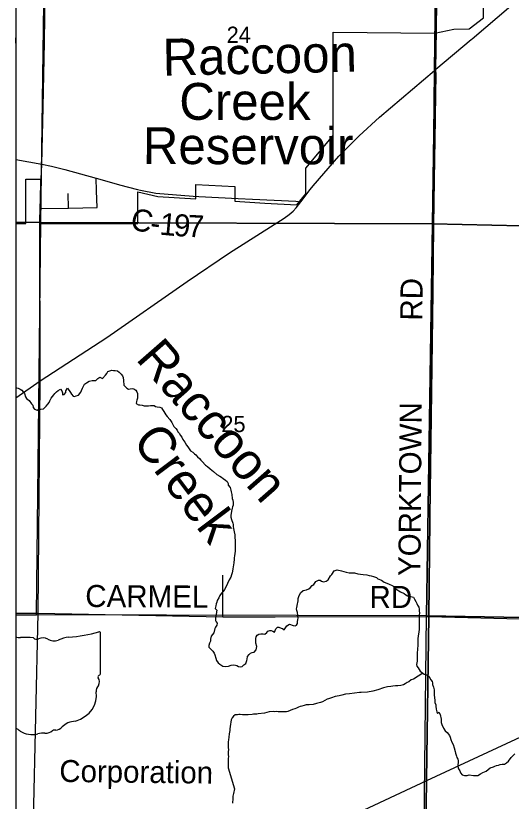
# Model space of a CAD drawing. Extents: x 0 to 34, y 0 to 22.
# Drawn here: x 2.1 to 3.375, y 14.74 to 16.762 of the extents above; entities that cross this region are included whole.
import ezdxf

# ---------------------------------------------------------------- set-up
doc = ezdxf.new("R2010")
doc.units = 0
for name, color, linetype in [('Default', 7, 'Continuous'), ('GM_X_City_Street', 7, 'Continuous'), ('GM_X_County_Road', 7, 'Continuous'), ('GM_X_County_Road_Text', 7, 'Continuous'), ('GM_X_Minor_Lake', 7, 'Continuous'), ('GM_X_Minor_Lake_Text', 7, 'Continuous'), ('GM_X_Minor_River', 7, 'Continuous'), ('GM_X_Minor_River_Text', 7, 'Continuous'), ('GM_X_Rail_Line_Text', 7, 'Continuous'), ('GM_X_Section', 7, 'Continuous'), ('GM_X_Section_Text', 7, 'Continuous'), ('GM_X_State_Location', 7, 'Continuous'), ('GM_X_State_Route', 7, 'Continuous'), ('GM_X_Township_Road', 7, 'Continuous'), ('GM_X_Township_Road_Text', 7, 'Continuous'), ('GM_X_Unincorporated_Text', 7, 'Continuous'), ('SH_Cut_Line', 7, 'Continuous'), ('SH_Data', 7, 'Continuous')]:
    doc.layers.add(name, color=color, linetype=linetype)

msp = doc.modelspace()

# ---------------------------------------------------------------- linework, layer by layer
at = {"layer": 'Default'}
msp.add_lwpolyline([(2.1, 18.4765), (2.1, 16.2268), (2.1261, 16.2272), (2.1261, 16.3412), (2.164, 16.3412), (2.1619, 16.2272), (2.4141, 16.2273), (2.4146, 16.3086), (2.4658, 16.2966), (2.5633, 16.2906), (2.5633, 16.3276), (2.664, 16.3223), (2.664, 16.2844), (2.741, 16.2797), (2.8235, 16.2748), (2.8465, 16.3036), (2.8465, 16.3697), (2.9169, 16.4536), (2.9169, 16.7199), (3.1786, 16.7169), (3.2272, 16.7274), (3.2668, 16.728), (3.3042, 16.7562), (3.3042, 16.7883)], dxfattribs=at)
for points in [[(2.1, 17.2332), (2.1, 16.2301), (2.1648, 16.2299), (2.1787, 17.2327)], [(2.1, 16.2301), (2.1, 15.22), (2.1535, 15.22), (2.1648, 16.2299)]]:
    msp.add_lwpolyline(points, close=True, dxfattribs=at)
at = {"layer": 'GM_X_City_Street'}
msp.add_line((2.236, 16.2668), (2.2354, 16.3044), dxfattribs=at)
for points in [[(2.3093, 16.2682), (2.3082, 16.3112), (2.3073, 16.3437)], [(2.1626, 16.2653), (2.236, 16.2668), (2.3093, 16.2682)]]:
    msp.add_lwpolyline(points, dxfattribs=at)
at = {"layer": 'GM_X_County_Road'}
for p, q in [((3.1811, 16.6243), (3.2725, 16.7007)), ((2.1, 16.3918), (2.1675, 16.3795)), ((2.8339, 16.2826), (2.8579, 16.3145)), ((2.5714, 16.2968), (2.6722, 16.2916)), ((2.1, 15.7781), (2.1627, 15.8218)), ((2.1481, 14.3195), (3.1578, 14.7935))]:
    msp.add_line(p, q, dxfattribs=at)
for points in [[(3.2725, 16.7007), (3.2748, 16.7027), (3.3741, 16.7874), (3.4093, 16.8175), (3.4389, 16.8423)], [(2.8579, 16.3145), (2.8651, 16.3241), (2.9317, 16.4007), (2.9842, 16.4531), (3.036, 16.5009), (3.1776, 16.6213), (3.1811, 16.6243)], [(2.1675, 16.3795), (2.192, 16.3743), (2.2263, 16.3658), (2.3073, 16.3437), (2.3528, 16.331)], [(2.3528, 16.331), (2.3673, 16.327), (2.4134, 16.3146), (2.4214, 16.313)], [(2.4214, 16.313), (2.4605, 16.3054), (2.5563, 16.2976), (2.5714, 16.2968)], [(2.1627, 15.8218), (2.3342, 15.9332), (2.541, 16.0775), (2.6502, 16.1519), (2.7651, 16.2248), (2.7906, 16.2409), (2.8037, 16.2498), (2.8142, 16.2591), (2.8217, 16.2673), (2.8339, 16.2826)], [(2.6722, 16.2916), (2.7095, 16.2897), (2.8212, 16.2843), (2.8339, 16.2826)], [(3.1578, 14.7935), (3.6526, 15.0232), (3.9337, 15.154), (4.0209, 15.1945), (4.1568, 15.2599), (4.2108, 15.2852), (4.2951, 15.3262), (4.5042, 15.4319), (4.6673, 15.5158)]]:
    msp.add_lwpolyline(points, dxfattribs=at)
at = {"layer": 'GM_X_Minor_Lake'}
for p, q in [((2.1, 16.691), (2.1002, 16.7053)), ((2.1002, 16.7053), (2.1, 16.7053))]:
    msp.add_line(p, q, dxfattribs=at)
at = {"layer": 'GM_X_Minor_River'}
msp.add_line((2.1002, 16.7053), (2.1002, 16.7053), dxfattribs=at)
for points in [[(2.2206, 15.7863), (2.2248, 15.7867), (2.2286, 15.7924), (2.2289, 15.7962), (2.2335, 15.803), (2.2407, 15.7921), (2.2434, 15.7875), (2.2476, 15.7826), (2.2514, 15.7819), (2.2556, 15.7834), (2.262, 15.7853), (2.2673, 15.7926), (2.2696, 15.7975), (2.2718, 15.8028), (2.2744, 15.8082), (2.2771, 15.8131), (2.282, 15.8169), (2.2888, 15.8212), (2.2968, 15.8227), (2.3028, 15.8231), (2.3066, 15.8228), (2.3112, 15.8281), (2.3168, 15.8312), (2.3233, 15.8278), (2.3308, 15.8366), (2.3346, 15.8411), (2.3369, 15.8457), (2.3426, 15.848), (2.3471, 15.8495), (2.3517, 15.8488), (2.3558, 15.8488), (2.3619, 15.8477), (2.3661, 15.8439), (2.3711, 15.8394), (2.3749, 15.8349), (2.3768, 15.8307), (2.3772, 15.8231), (2.3784, 15.8106), (2.3822, 15.8068), (2.3857, 15.803), (2.3906, 15.8004), (2.3944, 15.8015), (2.4001, 15.8019), (2.4039, 15.8016), (2.4089, 15.7982), (2.4119, 15.7933), (2.4135, 15.7891), (2.4135, 15.7815), (2.4131, 15.7773), (2.4113, 15.7724), (2.4109, 15.7686), (2.4102, 15.764), (2.4159, 15.7602), (2.4197, 15.7599), (2.4254, 15.7591), (2.4307, 15.758), (2.4356, 15.7573), (2.4417, 15.7577), (2.447, 15.7581), (2.4508, 15.7585), (2.4561, 15.7585), (2.4599, 15.7563), (2.4637, 15.7555), (2.4706, 15.754), (2.4751, 15.7522), (2.4778, 15.7484), (2.4813, 15.7427), (2.4839, 15.7385), (2.4862, 15.7343), (2.4901, 15.7298), (2.4962, 15.7222), (2.5015, 15.7151), (2.5034, 15.7113), (2.5073, 15.7048), (2.5122, 15.6991), (2.5153, 15.6946), (2.5176, 15.6908), (2.521, 15.687), (2.5241, 15.6813), (2.5275, 15.6772), (2.5302, 15.6711), (2.5356, 15.6639), (2.5398, 15.6567), (2.5428, 15.6522), (2.5463, 15.6473), (2.5501, 15.6416), (2.5554, 15.6382), (2.56, 15.6344), (2.5638, 15.6314), (2.5676, 15.6261), (2.573, 15.6219), (2.5764, 15.6182), (2.5795, 15.614), (2.5882, 15.6053), (2.5936, 15.6011), (2.6008, 15.5955), (2.6092, 15.5887), (2.618, 15.5811), (2.6252, 15.5766), (2.6294, 15.5736), (2.634, 15.5706)], [(2.1, 15.8053), (2.1021, 15.8036), (2.1059, 15.8028), (2.1112, 15.8009), (2.1154, 15.7979), (2.1189, 15.7938), (2.1223, 15.7892), (2.125, 15.7805), (2.1281, 15.7763), (2.1346, 15.771), (2.141, 15.7631), (2.1437, 15.7593), (2.1449, 15.7532), (2.148, 15.7491), (2.1552, 15.7468), (2.1597, 15.7491), (2.1646, 15.7495), (2.1711, 15.7499), (2.1783, 15.7572), (2.1824, 15.7621), (2.1858, 15.7663), (2.1881, 15.7705), (2.1911, 15.7774), (2.1979, 15.7858), (2.2005, 15.7896), (2.2047, 15.7938), (2.2096, 15.7972), (2.2153, 15.8003), (2.2191, 15.7961), (2.2206, 15.7912), (2.2206, 15.7863)], [(2.634, 15.5706), (2.6397, 15.566), (2.6439, 15.5626), (2.6466, 15.5577), (2.647, 15.5535), (2.6515, 15.5471), (2.6539, 15.5403), (2.6546, 15.5365), (2.6558, 15.5293), (2.6574, 15.5194), (2.6585, 15.5148), (2.6597, 15.5092), (2.6594, 15.5023), (2.6579, 15.4977), (2.6567, 15.4939), (2.6553, 15.4863), (2.6542, 15.4803), (2.6538, 15.4765), (2.6538, 15.4708), (2.6554, 15.4647), (2.6585, 15.456), (2.6592, 15.4522), (2.66, 15.4472), (2.6604, 15.4415), (2.6624, 15.4332), (2.6639, 15.4256), (2.6643, 15.421), (2.6644, 15.4085), (2.6648, 15.4032), (2.6644, 15.3979), (2.6649, 15.3891), (2.6649, 15.3827), (2.6638, 15.3781), (2.6627, 15.3709), (2.6623, 15.3671), (2.662, 15.3618), (2.6612, 15.3542), (2.6601, 15.3477), (2.6594, 15.3439), (2.6591, 15.3374), (2.6572, 15.3279), (2.6557, 15.3226), (2.6535, 15.3169), (2.6497, 15.31), (2.6452, 15.3005), (2.6411, 15.291), (2.6377, 15.2845), (2.6335, 15.2796), (2.6294, 15.2758), (2.6252, 15.2693), (2.623, 15.2632), (2.6188, 15.2567), (2.6173, 15.2522), (2.6162, 15.248), (2.6147, 15.243), (2.6136, 15.2358), (2.6178, 15.232), (2.6171, 15.2275), (2.6156, 15.2199), (2.6153, 15.2161), (2.6141, 15.2107), (2.6145, 15.2054), (2.6157, 15.2016), (2.6188, 15.1978), (2.6177, 15.1929), (2.6139, 15.1883), (2.6124, 15.1845), (2.6098, 15.1735), (2.603, 15.1647), (2.6015, 15.1567), (2.6012, 15.1522), (2.5985, 15.1468), (2.597, 15.1411), (2.5974, 15.1362), (2.6009, 15.1324), (2.6074, 15.1264), (2.6104, 15.1211), (2.6127, 15.1165), (2.6154, 15.1082), (2.617, 15.1021), (2.6208, 15.0964), (2.6257, 15.0923), (2.6326, 15.0877), (2.6391, 15.087), (2.6478, 15.0874), (2.6546, 15.0901), (2.6614, 15.0913), (2.6656, 15.0902), (2.6694, 15.0891), (2.6732, 15.0868), (2.6782, 15.0861), (2.6827, 15.0868), (2.6869, 15.0907), (2.6922, 15.0945), (2.6952, 15.1017), (2.6959, 15.1055), (2.6966, 15.1124), (2.7004, 15.1173), (2.7038, 15.1211), (2.7087, 15.1223), (2.7137, 15.1231)], [(2.7137, 15.1231), (2.7189, 15.1296), (2.7197, 15.1334), (2.7204, 15.1383), (2.7177, 15.147), (2.7177, 15.1584), (2.7184, 15.1626), (2.7218, 15.1672), (2.7259, 15.1695), (2.7309, 15.1706), (2.737, 15.1703), (2.7411, 15.1695), (2.746, 15.1738), (2.7491, 15.1779), (2.7536, 15.1791), (2.7574, 15.1791), (2.762, 15.1772), (2.7658, 15.1754), (2.7695, 15.1834), (2.7733, 15.1879), (2.7771, 15.1876), (2.7828, 15.1857), (2.787, 15.1842), (2.7912, 15.1812), (2.7976, 15.1915), (2.8044, 15.1953), (2.8143, 15.1923), (2.8188, 15.1912), (2.823, 15.1931), (2.8253, 15.1973), (2.8252, 15.2015), (2.8263, 15.2072), (2.8267, 15.2114), (2.8263, 15.2186), (2.8251, 15.2258), (2.8236, 15.2307), (2.8228, 15.2349), (2.8232, 15.2387), (2.825, 15.2478), (2.8257, 15.2516), (2.8269, 15.2558), (2.8272, 15.2619), (2.8283, 15.2668), (2.8328, 15.2764), (2.8396, 15.2825), (2.8487, 15.284), (2.8544, 15.2867), (2.8582, 15.2894), (2.8631, 15.2951), (2.8669, 15.2978), (2.8725, 15.3054), (2.8794, 15.3085), (2.8832, 15.3085), (2.8873, 15.3066), (2.8923, 15.3047), (2.8987, 15.3059), (2.9044, 15.3101), (2.9097, 15.3196), (2.9134, 15.3235), (2.9199, 15.3326), (2.9271, 15.3353), (2.9381, 15.3327), (2.9502, 15.3297), (2.9582, 15.3275), (2.9624, 15.3279), (2.9719, 15.3279), (2.9802, 15.3249), (2.9871, 15.3242), (2.9939, 15.3238), (3.0034, 15.3228), (3.0095, 15.3209), (3.0148, 15.3198), (3.0205, 15.3179), (3.0281, 15.3157), (3.0323, 15.3126), (3.0414, 15.3089), (3.0483, 15.304), (3.0593, 15.2995), (3.0707, 15.2942), (3.0795, 15.2859), (3.0902, 15.2787), (3.0997, 15.2746), (3.1039, 15.2708), (3.1085, 15.2689), (3.113, 15.2667), (3.1172, 15.2667), (3.1237, 15.2648), (3.1263, 15.2603), (3.1294, 15.2542), (3.1325, 15.2489), (3.134, 15.2447), (3.1371, 15.2394), (3.1382, 15.2341), (3.1386, 15.23), (3.139, 15.2243), (3.1387, 15.2197), (3.138, 15.2117), (3.1381, 15.1939), (3.1385, 15.1863), (3.1385, 15.1821), (3.1374, 15.176)], [(3.1374, 15.176), (3.1359, 15.165), (3.1352, 15.1585), (3.1352, 15.1509), (3.1349, 15.1471), (3.1345, 15.1395), (3.1338, 15.1331), (3.1338, 15.1285), (3.1335, 15.1239), (3.1331, 15.1167), (3.1332, 15.1057), (3.1328, 15.1), (3.1325, 15.0958), (3.1317, 15.0916), (3.1325, 15.0871), (3.1356, 15.0833), (3.1413, 15.075), (3.1508, 15.0667), (3.1577, 15.0648), (3.1634, 15.0614), (3.168, 15.0523), (3.1714, 15.0481), (3.1722, 15.0443), (3.1726, 15.0402), (3.1753, 15.0333), (3.1769, 15.0269), (3.1769, 15.0125), (3.1777, 15.0068), (3.1785, 14.9992), (3.1789, 14.9939), (3.1812, 14.9882), (3.1812, 14.9844), (3.1817, 14.9764), (3.184, 14.9703), (3.1855, 14.9658), (3.1893, 14.9688), (3.1927, 14.9628), (3.1947, 14.9514), (3.1947, 14.9423), (3.1963, 14.937), (3.2005, 14.9279), (3.2055, 14.921), (3.2104, 14.9165), (3.2166, 14.9086), (3.2177, 14.9048), (3.2196, 14.8991), (3.2223, 14.8915), (3.2254, 14.8858), (3.2285, 14.8771), (3.2308, 14.8676), (3.2316, 14.8634), (3.2343, 14.8562), (3.2354, 14.8521), (3.2381, 14.8483), (3.2385, 14.8445), (3.2385, 14.8403), (3.2378, 14.8327), (3.2382, 14.8289), (3.2398, 14.8228), (3.2428, 14.8183), (3.2447, 14.813), (3.2489, 14.8081), (3.255, 14.8058), (3.2619, 14.8062), (3.2672, 14.8081), (3.2778, 14.8063), (3.282, 14.8056), (3.2892, 14.8063), (3.2964, 14.8106), (3.3024, 14.814), (3.3104, 14.8175), (3.3157, 14.8213), (3.3214, 14.8255), (3.3293, 14.8282), (3.3331, 14.8297), (3.3376, 14.832), (3.3422, 14.8328), (3.3471, 14.8347), (3.3521, 14.8348), (3.3577, 14.8352), (3.3634, 14.839), (3.3683, 14.8432), (3.3751, 14.852), (3.3849, 14.8615)], [(3.1477, 15.0694), (3.124, 15.0544), (3.1179, 15.0521), (3.1118, 15.0471), (3.1077, 15.0456), (3.1024, 15.0421), (3.0978, 15.0394), (3.091, 15.0375), (3.0831, 15.0367), (3.077, 15.0367), (3.0705, 15.0363), (3.0652, 15.0355), (3.0569, 15.0347), (3.0466, 15.032), (3.0322, 15.0266), (3.0193, 15.0235), (3.0057, 15.0208), (2.989, 15.0195), (2.9848, 15.0195), (2.9719, 15.0183), (2.9594, 15.016), (2.9488, 15.0152), (2.9389, 15.0132), (2.9325, 15.0109), (2.9222, 15.009), (2.9131, 15.0063), (2.9052, 15.0036), (2.9014, 15.0024), (2.8957, 14.9993), (2.8893, 14.9959), (2.8844, 14.9936), (2.8737, 14.9913), (2.8658, 14.9886), (2.8552, 14.9881), (2.8472, 14.9877), (2.8426, 14.9866), (2.8362, 14.9846), (2.8324, 14.9835), (2.8279, 14.9819), (2.8229, 14.9792), (2.818, 14.9773), (2.8123, 14.9758), (2.8063, 14.9735), (2.8006, 14.9712), (2.7968, 14.97), (2.7903, 14.97), (2.7801, 14.9699), (2.7752, 14.9703), (2.7714, 14.9706), (2.7672, 14.9702), (2.7623, 14.9706), (2.752, 14.9702), (2.7399, 14.9663), (2.7243, 14.9647), (2.7205, 14.9643), (2.7122, 14.9635), (2.7084, 14.9627), (2.6985, 14.9619), (2.6902, 14.9619), (2.6837, 14.9626), (2.678, 14.963), (2.6742, 14.963), (2.6704, 14.9626), (2.6644, 14.9625), (2.6602, 14.9587), (2.6568, 14.9545), (2.6549, 14.9496), (2.6535, 14.9435), (2.6527, 14.9382), (2.6513, 14.926), (2.6509, 14.9218), (2.6494, 14.9135), (2.6483, 14.9051), (2.6472, 14.8982), (2.6469, 14.8925), (2.6469, 14.8781), (2.6474, 14.8724), (2.647, 14.8675), (2.647, 14.8595), (2.6474, 14.8546), (2.6471, 14.8496), (2.6467, 14.8439), (2.6464, 14.839), (2.6464, 14.8352), (2.6465, 14.8261)], [(2.6465, 14.8261), (2.6627, 14.7718), (2.6601, 14.7593), (2.659, 14.7524), (2.659, 14.7467), (2.6575, 14.7346)]]:
    msp.add_lwpolyline(points, dxfattribs=at)
at = {"layer": 'GM_X_Section'}
for points in [[(3.1868, 17.2222), (3.1722, 16.2262), (2.1648, 16.2299), (2.1787, 17.2327)], [(3.1868, 17.2222), (4.1831, 17.1984), (4.1651, 16.2036), (3.1722, 16.2262)], [(3.1722, 16.2262), (3.1571, 15.217), (2.1535, 15.22), (2.1648, 16.2299)], [(4.1651, 16.2036), (4.1541, 15.2001), (3.1571, 15.217), (3.1722, 16.2262)], [(3.1571, 15.217), (4.1541, 15.2001), (4.1481, 14.2013), (3.1458, 14.2165)]]:
    msp.add_lwpolyline(points, close=True, dxfattribs=at)
at = {"layer": 'GM_X_State_Route'}
msp.add_line((2.1388, 14.359), (2.1579, 15.2243), dxfattribs=at)
for points in [[(2.1659, 16.3414), (2.1675, 16.3795), (2.1709, 16.5269), (2.1739, 16.694), (2.1758, 16.8248), (2.1778, 16.954), (2.178, 16.9829), (2.1783, 17.0109), (2.1791, 17.0536), (2.1796, 17.1266), (2.1796, 17.1276)], [(2.1622, 16.2348), (2.1626, 16.2653), (2.1659, 16.3414)], [(2.1579, 15.2243), (2.1627, 15.8218), (2.1622, 16.2348)]]:
    msp.add_lwpolyline(points, dxfattribs=at)
at = {"layer": 'GM_X_Township_Road'}
for p, q in [((3.1811, 16.6243), (3.1825, 16.7248)), ((2.6334, 15.2146), (2.6333, 15.322)), ((2.1, 15.2242), (2.1579, 15.2243)), ((2.7679, 15.2148), (3.163, 15.2153))]:
    msp.add_line(p, q, dxfattribs=at)
for points in [[(3.1491, 14.2171), (3.1576, 14.794), (3.1628, 15.2158), (3.1774, 16.6199), (3.1774, 16.6219), (3.1894, 17.563), (3.1895, 17.5705), (3.1896, 17.5787), (3.2069, 18.535), (3.2116, 19.2346), (3.2118, 19.2455), (3.2241, 20.2443), (2.209, 20.2314), (2.1, 20.2296), (2.1, 14.2219)], [(8.9, 14.1483), (8.9, 20.2053), (7.2271, 20.2132), (6.4763, 20.2191), (6.0936, 20.222), (5.2207, 20.2288), (4.224, 20.2365), (3.2241, 20.2443), (3.2118, 19.2455), (3.2116, 19.2346), (3.2069, 18.535), (3.1896, 17.5787), (3.1895, 17.5705), (3.1894, 17.563), (3.1774, 16.6219), (3.1774, 16.6199), (3.1628, 15.2158), (3.1576, 14.794), (3.1491, 14.2171)], [(3.1825, 16.7248), (3.1856, 16.949), (3.1895, 17.2331), (3.1886, 17.3226), (3.1881, 17.4029), (3.1894, 17.4385), (3.1927, 17.509), (3.1936, 17.5489), (3.1942, 17.5683)], [(3.1761, 16.2216), (3.1774, 16.3393), (3.1806, 16.4968), (3.1812, 16.5616), (3.1819, 16.6084), (3.1811, 16.6243)], [(3.163, 15.2153), (3.1742, 16.0515), (3.1761, 16.2216)], [(2.1579, 15.2243), (2.6334, 15.2146), (2.7679, 15.2148)], [(3.1493, 14.2166), (3.1578, 14.7935), (3.163, 15.2153)], [(3.163, 15.2153), (3.8988, 15.1968), (3.933, 15.1962), (4.0209, 15.1945)]]:
    msp.add_lwpolyline(points, dxfattribs=at)
at = {"layer": 'GM_X_Unincorporated_Text'}
msp.add_line((2.1, 15.1625), (2.1, 14.9274), dxfattribs=at)
msp.add_lwpolyline([(2.3183, 15.0678), (2.3182, 15.0678), (2.3183, 15.0678), (2.3183, 15.1726)], dxfattribs=at)
for centre, major_axis, start_param, end_param in [((2.2009, 15.4403), (0.3495, 0), 4.814394, 5.042369), ((2.3146, 15.1729), (0.00367, 0), 6.197627, 7.989034), ((2.1114, 15.1907), (0.037, 0), 4.398293, 4.731792), ((2.1237, 15.0551), (0.133, 0), 1.404758, 1.657859), ((2.1539, 15.1655), (0.0107, 0), 3.836095, 5.185415), ((2.1696, 15.1424), (0.0222, 0), 0.950623, 2.079405), ((2.1983, 15.1741), (0.0267, 0), 4.08156, 5.145723), ((2.2455, 15.1064), (0.0703, 0), 1.699012, 2.107814), ((2.3144, 15.0674), (0.00393, 0), 5.05454, 6.418171), ((2.3174, 15.0601), (0.00568, 0), 1.883978, 3.671073), ((2.2813, 15.0468), (0.0341, 0), 5.934695, 6.695948), ((2.3314, 15.0239), (0.0248, 0), 2.387724, 3.262537), ((2.2205, 15.0106), (0.0874, 0), 5.101753, 6.440018), ((2.2573, 14.9077), (0.0479, 0), 1.647645, 2.488434), ((2.0577, 14.874), (0.079, 0), 0.823519, 1.005151), ((2.1966, 14.9445), (0.0282, 0), 4.937069, 5.64225), ((2.1431, 14.9514), (0.0501, 0), 4.026481, 4.996735), ((2.172, 14.8822), (0.0412, 0), 1.495662, 1.94098), ((2.1757, 14.9364), (0.0267, 0), 4.691044, 5.507374), ((2.1999, 14.917), (0.00752, 0), 1.147584, 2.315152)]:
    msp.add_ellipse(centre, major_axis=major_axis, ratio=0.8, start_param=start_param, end_param=end_param, dxfattribs=at)
at = {"layer": 'SH_Cut_Line'}
msp.add_lwpolyline([(8.9, 14.1483), (8.9, 20.9), (2.1, 20.9), (2.1, 14.2219)], dxfattribs=at)
at = {"layer": 'SH_Data'}
msp.add_line((2.1, 20.9), (2.1, 14.1), dxfattribs=at)

# ---------------------------------------------------------------- texts
at = {"layer": 'GM_X_County_Road_Text'}
for s, rotation, p in [('C', 346.5317, (2.3917, 16.2137)), ('1', 354.5927, (2.4688, 16.1986)), ('9', 356.365, (2.5056, 16.1951)), ('7', 356.8303, (2.541, 16.1929)), ('-', 353.0323, (2.444, 16.2016))]:
    msp.add_text(s, height=0.0568, rotation=rotation, dxfattribs=at).set_placement(p)
at = {"layer": 'GM_X_Minor_Lake_Text'}
for s, rotation, p in [('Raccoon', 1.178, (2.4788, 16.6076)), ('Creek', 359.8958, (2.5209, 16.4941)), ('Reservoir', 359.896, (2.427, 16.3802))]:
    msp.add_text(s, height=0.09475, rotation=rotation, dxfattribs=at).set_placement(p)
at = {"layer": 'GM_X_Minor_River_Text'}
for s, rotation, p in [('Raccoon', 311.1758, (2.4068, 15.8777)), ('Creek', 306.8935, (2.3976, 15.6666))]:
    msp.add_text(s, height=0.09475, rotation=rotation, dxfattribs=at).set_placement(p)
at = {"layer": 'GM_X_Rail_Line_Text'}
msp.add_text('Corporation', height=0.056629, rotation=359.3593, dxfattribs=at).set_placement((2.212, 14.7895))
at = {"layer": 'GM_X_Section_Text'}
for s, p in [('24', (2.6429, 16.692)), ('25', (2.6292, 15.69))]:
    msp.add_text(s, height=0.04186, rotation=0, dxfattribs=at).set_placement(p)
at = {"layer": 'GM_X_State_Location'}
for s in ['s', 'r']:
    msp.add_text(s, height=0.000189, dxfattribs=at).set_placement((2.1498, 15.0507))
at = {"layer": 'GM_X_Township_Road_Text'}
for s, rotation, p in [('RD', 89.5045, (3.1464, 15.9768)), ('YORKTOWN', 89.5287, (3.1414, 15.3193)), ('CARMEL', 359.6789, (2.2789, 15.2398)), ('RD', 0, (3.0104, 15.2373))]:
    msp.add_text(s, height=0.05682, rotation=rotation, dxfattribs=at).set_placement(p)

doc.saveas('drawing.dxf')
